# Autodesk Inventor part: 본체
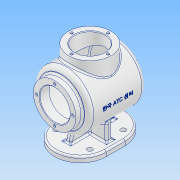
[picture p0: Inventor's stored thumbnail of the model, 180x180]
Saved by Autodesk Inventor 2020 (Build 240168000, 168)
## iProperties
Created: 2023-01
Part Number: 본체
Material: 알루미늄 6061
Document SubType Name: Modeling
Designer: user
Density: 2.7 g/cm^3
Appearance: 알루미늄 - 평지
Mass: 1048.87 g
Surface Area: 1154.36 cm^2
Volume: 388.471 cm^3
Author: user
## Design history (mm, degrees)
sketch "스케치3"
  geometry: L1 (46, -63)-(-46, -63); L2 (-46, -63)-(-46, 63); L3 (-46, 63)-(46, 63); L4 (46, 63)-(46, -63); L5 (46, -63)-(-46, 63); L6 (-46, -63)-(46, 63); 1 further point
  constraints: 12 end point, 2 midpoint, 2 parallel, 1 horizontal, 1 perpendicular
  dimensions: "d3" = 92 distance of L2.end L3.end; "d4" = 126 distance of L1.end L2.end
extrude "돌출1" new body sketch "스케치3" distance "d5" = 10; taper "d6" = 0 deg
fillet "모깎기1" dims "d7" = 46
fillet "모깎기2" dims "d8" = 46
sketch "스케치4"
  geometry: L1 (0, 0)-(30, 0); L2 (30, 0)-(30, -30); L3 (30, -30)-(0, -30); L4 (0, -30)-(0, 0); C1 r 4.5 at (30, -30)
  constraints: 8 end point, 2 parallel, 1 centre point, 1 coincident, 1 horizontal, 1 perpendicular
  dimensions: "d9" = 30 distance of L2.end L3.end; "d10" = 30 distance of L1.end L2.end; "d11" = 9 diameter of C1
extrude "돌출2" cut sketch "스케치4" extent not by distance; stored distance "d12" = 0; taper "d13" = 0 deg
sketch "스케치5"
  geometry: L1 (0, 0)-(-30, 0); L2 (-30, 0)-(-30, -30); L3 (-30, -30)-(0, -30); L4 (0, -30)-(0, 0); C1 r 4.5 at (-30, -30)
  constraints: 8 end point, 2 parallel, 1 centre point, 1 coincident, 1 horizontal, 1 perpendicular
  dimensions: "d14" = 30 distance of L3.end L2.end; "d15" = 30 distance of L2.end L1.end; "d16" = 9 diameter of C1
extrude "돌출3" cut sketch "스케치5" extent not by distance; stored distance "d17" = 0; taper "d18" = 0 deg
sketch "스케치6"
  geometry: L1 (0, 0)-(-30, 0); L2 (-30, 0)-(-30, 30); L3 (-30, 30)-(0, 30); L4 (0, 30)-(0, 0); L5 (0, 0)-(30, 0); L6 (30, 0)-(30, 30); L7 (30, 30)-(0, 30); L8 (0, 30)-(0, 0); C1 r 4.5 at (-30, 30); C2 r 4.5 at (30, 30)
  constraints: 16 end point, 4 parallel, 2 centre point, 2 coincident, 2 horizontal, 2 perpendicular
  dimensions: "d19" = 30 distance of L2.end L3.end; "d20" = 30 distance of L1.end L2.end; "d21" = 30 distance of L7.end L6.end; "d22" = 30 distance of L6.end L5.end; "d23" = 9 diameter of C1; "d24" = 9 diameter of C2
extrude "돌출4" cut sketch "스케치6" extent not by distance; stored distance "d25" = 0; taper "d26" = 0 deg
sketch "스케치7"
  geometry: L1 (0, 0)-(80, 0); L2 (80, 0)-(80, 63); L3 (80, 63)-(118, 63); L4 (118, 63)-(118, 51); L5 (118, 51)-(80, 51)
  constraints: 10 end point, 3 perpendicular, 2 horizontal, 1 point on line
  dimensions: "d27" = 80 distance of L1.start L1.end; "d28" = 63 distance of L1.end L2.end; "d29" = 38 distance of L2.end L3.end; "d30" = 12 distance of L3.end L4.end
revolve "회전1" sketch "스케치7" stored, may be unused: angle "d31" = 90 deg
sketch "스케치8"
  geometry: L1 (42, 63)-(118, 63) reference; L2 (42, 51)-(118, 51) reference; L3 (80, 51)-(130, 51); L4 (130, 51)-(130, -48.283); L5 (80, 51)-(80, -59); A1 r 122 centre (80, 63) between (130, -48.283) and (80, -59); 2 further points
  constraints: 6 end point, 2 midpoint, 2 point on circle, 1 centre point, 1 parallel, 1 perpendicular, 1 point on line
  dimensions: "d32" = 244 diameter of A1; "d33" = 50 distance of L3.start L3.end
revolve "회전2" sketch "스케치8" stored, may be unused: angle "d34" = 90 deg
sketch "스케치9"
  geometry: L1 (0, 0)-(144, 0); L2 (144, 0)-(144, 38); L3 (144, 38)-(94.086, 38); L4 (94.086, 38)-(94.086, 0)
  constraints: 8 end point, 3 perpendicular, 1 horizontal, 1 point on line
  dimensions: "d35" = 144 distance of L1.start L1.end; "d36" = 38 distance of L1.end L2.end
revolve "회전3" sketch "스케치9" stored, may be unused: angle "d37" = 90 deg
sketch "스케치10"
  geometry: L1 (50, -51)-(-50, -51) reference; L2 (35, 0)-(35, 5); L3 (35, 5)-(-35, 5); L4 (-35, 5)-(-35, -5); L5 (-35, -5)-(35, -5); L6 (35, -5)-(35, 0); 1 further point
  constraints: 10 end point, 1 perpendicular, 1 point on line, 1 vertical
extrude "돌출5" join sketch "스케치10" distance "d43" = 64.5; taper "d44" = 0 deg
sketch "스케치11"
  geometry: L1 (10, 63)-(10, 17) reference; L2 (10, 63)-(10, 40); L3 (10, 40)-(45.674, 30.441); L4 (45.674, 30.441)-(45.674, 0); L5 (45.674, 0)-(4.837, 0); L6 (4.837, 0)-(4.837, 40); L7 (4.837, 40)-(10, 40); 1 further point
  constraints: 12 end point, 3 perpendicular, 1 midpoint, 1 parallel
  dimensions: "d45" = 23 distance of L1.start L2.end; "d46" = 105 deg angle of L3 L2
extrude "돌출6" join sketch "스케치11" stored distance "d47" = 10; taper "d48" = 0 deg
sketch "스케치12"
  geometry: L1 (10, 63)-(10, 17) reference; L2 (10, 17)-(10, -17) reference; L3 (10, 63)-(10, -40); L4 (10, -17)-(10, -63) reference; L5 (10, -40)-(53.269, -28.406); L6 (10, -40)-(54.795, -40); L7 (53.269, -28.406)-(53.269, 0); L8 (53.269, 0)-(5.759, 0); L9 (5.759, 0)-(5.759, -40); L10 (5.759, -40)-(10, -40); 3 further points
  constraints: 14 end point, 3 perpendicular, 1 equal length, 1 horizontal, 1 midpoint, 1 vertical
  dimensions: "d49" = 103 distance of L1.start L3.end (derived); "d51" = 15 deg angle of L6 L5
extrude "돌출7" join sketch "스케치12" stored distance "d52" = 10; taper "d53" = 0 deg
sketch "스케치13"
  geometry: C1 r 38 at (0, 0) reference; C2 r 27 at (0, 0); 1 further point
  constraints: 1 centre point, 1 coincident
  dimensions: "d54" = 54 diameter of C2
extrude "돌출8" cut sketch "스케치13" distance "d55" = 17; taper "d56" = 0 deg
sketch "스케치15"
  geometry: L1 (53, 46)-(107, 46) reference; L2 (80, 46)-(125, 46); L3 (125, 46)-(125, -43.303); L4 (80, 46)-(80, -54); A1 r 100 centre (80, 46) between (80, -54) and (125, -43.303); 3 further points
  constraints: 6 end point, 2 point on circle, 1 centre point, 1 coincident, 1 horizontal, 1 midpoint, 1 vertical
revolve "회전4" sketch "스케치15" stored, may be unused: angle "d59" = 90 deg
sketch "스케치16"
  geometry: C1 r 38 at (0, 0) reference; C2 r 27 at (0, 0)
  constraints: 1 centre point, 1 coincident
  dimensions: "d60" = 54 diameter of C2
extrude "돌출9" cut sketch "스케치16" distance "d61" = 66.75; taper "d62" = 0 deg
sketch "스케치17" dims "d63" = 65
  geometry: L1 (0, 0)-(0, 32.5); C1 r 38 at (0, 0) reference; 1 further point
  constraints: 2 end point, 1 coincident, 1 vertical alignment, 2 other
hole "구멍1" sketch "스케치17" at (0, 32.5) diameter "d64" = 3.242; stored, may be unused: countersink angle "d68" = 90 deg, drill point angle "d70" = 118 deg; dims "d65" = 8, "d66" = 5, "d67" = 4.775, "d69" = 10
sketch "스케치19" dims "d74" = 65
  geometry: L1 (0, 0)-(0, 32.5); C1 r 38 at (0, 0) reference
  constraints: 2 end point, 1 coincident, 1 vertical alignment, 2 other
hole "구멍2" sketch "스케치19" at (0, 32.5) diameter "d75" = 3.242; stored, may be unused: countersink angle "d79" = 90 deg, drill point angle "d81" = 118 deg; dims "d76" = 8, "d77" = 5, "d78" = 4.775, "d80" = 10
chamfer "모따기1" distance "d85" = 1; stored, may be unused: second distance "d86" = 2, angle "d87" = 45 deg
fillet "모깎기3" dims "d88" = 3
fillet "모깎기4" dims "d89" = 8
fillet "모깎기5" dims "d90" = 3
fillet "모깎기6" dims "d91" = 3
fillet "모깎기7" dims "d92" = 3
fillet "모깎기8" dims "d93" = 3
fillet "모깎기9" dims "d94" = 3
fillet "모깎기10" dims "d95" = 3
fillet "모깎기11" dims "d96" = 3
node "작업 평면1"
sketch "스케치20"
  geometry: L1 (3, 26.07)-(3, -28.787); L2 (3, -28.787)-(-3, -28.787); L3 (-3, -28.787)-(-3, 26.07); L4 (-3, 26.07)-(3, 26.07); L5 (-38, 61.642)-(38, 61.642) reference; L6 (50, 41.642)-(-50, 41.642) reference; 3 further points
  constraints: 2 midpoint, 2 other
  dimensions: "d102" = 6 distance of point (-3, -1.358) point (3, -1.358); "d103" = 63 distance from line of L5 point (-3, -1.358); "d104" = 77 distance of point (-80, -1.358) point (-3, -1.358)
feature "엠보싱1" sketch "스케치20" dims "d9" = 30, "d10" = 30, "d11" = 9, "d105" = 0.5, "d106" = 0
node "솔리드1"
pattern_circular "원형 패턴1" dims angle "d72" = 360 deg
pattern_circular "원형 패턴2" dims angle "d83" = 360 deg
feature "A9D066F2-1C7D-4E18-AEED-F7BC21143FA4" dims "d64" = 3.242, "d65" = 8, "d66" = 5, "d67" = 4.775, "d68" = 90 deg, "d69" = 10, "d70" = 118 deg
